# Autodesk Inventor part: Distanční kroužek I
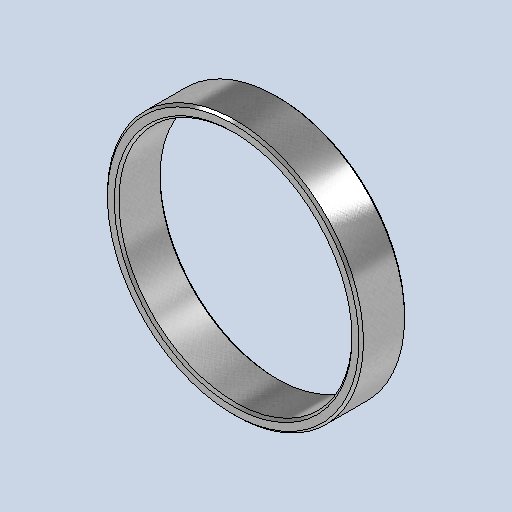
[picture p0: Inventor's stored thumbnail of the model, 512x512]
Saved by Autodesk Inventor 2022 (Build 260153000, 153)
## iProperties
Created: 2025-05
Part Number: Distanční kroužek I
Material: Všeobecné
Document SubType Name: Modeling
Designer: jbart
Density: 1 g/cm^3
Appearance: Broušená
Mass: 4.11784 g
Surface Area: 40.0497 cm^2
Volume: 4.11784 cm^3
Author: jbart
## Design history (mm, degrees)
sketch "Náčrt1"
  geometry: C1 r 25.5 at (0, 0); C2 r 28 at (0, 0); 1 further point
  constraints: 2 centre point, 2 coincident
  dimensions: "d0" = 51 diameter of C1; "d1" = 56 diameter of C2
extrude "Vysunutí1" new body sketch "Náčrt1" distance "d2" = 10; taper "d3" = 0 deg
chamfer "Zkosení1" distance "d4" = 0.5; stored, may be unused: second distance "d5" = 2, angle "d6" = 45 deg
node "Těleso1"
